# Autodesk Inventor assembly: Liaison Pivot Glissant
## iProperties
Shininess: 21.0
Length Units: 11269
Angle Units: 11279
Time Units: 11290
Mass Units: 11283
Length Display Precision: 3
Angle Display Precision: 2
Created: 2002-01
Part Number: Liaison Pivot Glissant
Document SubType Name: Assemblage
Designer: Chris...
Density: 0.0
Volumn: 0.0
Area: 0.0
PropertySet Name: Model Information
Control State: 0
Master: False
Checked Out: False
Author: Chris...
